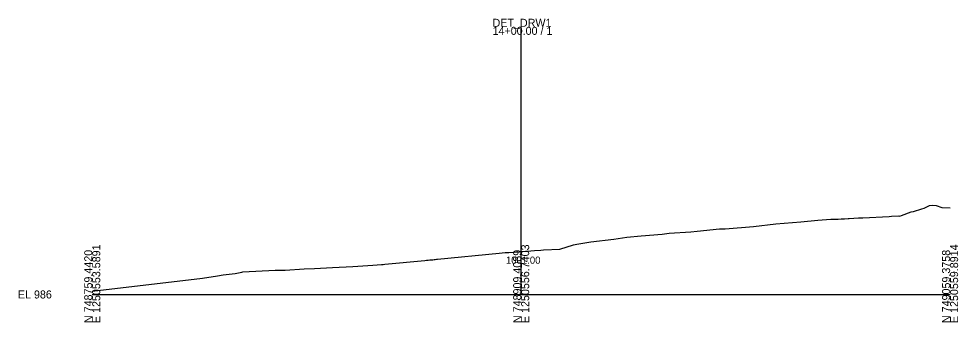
# Model space of a CAD drawing. Extents: x -26 to 303, y -259 to 4096.
# Drawn here: x -25.7 to 302.8, y 3990.3 to 4096.3 of the extents above; entities that cross this region are included whole.
import ezdxf

# ---------------------------------------------------------------- set-up
doc = ezdxf.new("R2010")
doc.units = 0
for name, color, linetype in [('Default', 7, 'Continuous'), ('Exist Cross Section Cell', 7, 'Continuous'), ('Exist XS Center Line Elevation Label', 7, 'Continuous'), ('Exist XS Ground Line', 7, 'Continuous')]:
    doc.layers.add(name, color=color, linetype=linetype)

msp = doc.modelspace()

# ---------------------------------------------------------------- linework, layer by layer
at = {"layer": 'Exist Cross Section Cell'}
for p, q in [((150, 4000), (150, 4093.54)), ((0, 4000), (150, 4000)), ((150, 4000), (300, 4000))]:
    msp.add_line(p, q, dxfattribs=at)
at = {"layer": 'Exist XS Ground Line'}
for p, q in [((290.94, 4030.11), (292.84, 4031.1)), ((292.84, 4031.1), (294.01, 4031.18)), ((294.01, 4031.18), (295.09, 4031.12)), ((295.09, 4031.12), (297.1, 4030.4)), ((282.98, 4027.64), (286.39, 4028.84)), ((286.39, 4028.84), (287.24, 4029.02)), ((287.24, 4029.02), (290.17, 4029.9)), ((290.17, 4029.9), (290.94, 4030.11)), ((297.1, 4030.4), (300, 4030.33)), ((231.2, 4023.81), (239.07, 4024.66)), ((239.07, 4024.66), (247.78, 4025.38)), ((247.78, 4025.38), (253.7, 4026.01)), ((253.7, 4026.01), (258.32, 4026.37)), ((258.32, 4026.37), (260.91, 4026.37)), ((260.91, 4026.37), (261.86, 4026.41)), ((261.86, 4026.41), (263.1, 4026.48)), ((263.1, 4026.48), (264.36, 4026.58)), ((264.36, 4026.58), (264.73, 4026.55)), ((264.73, 4026.55), (267.99, 4026.73)), ((267.99, 4026.73), (269.49, 4026.81)), ((269.49, 4026.81), (278.7, 4027.21)), ((278.7, 4027.21), (279.47, 4027.33)), ((279.47, 4027.33), (282.11, 4027.43)), ((282.11, 4027.43), (282.41, 4027.34)), ((282.41, 4027.34), (282.98, 4027.64)), ((199.32, 4021.05), (201.8, 4021.37)), ((201.8, 4021.37), (209.32, 4021.93)), ((209.32, 4021.93), (211.59, 4022.07)), ((211.59, 4022.07), (219.33, 4022.88)), ((219.33, 4022.88), (221.39, 4022.99)), ((221.39, 4022.99), (231.2, 4023.81)), ((169.41, 4017.62), (174.39, 4018.37)), ((174.39, 4018.37), (182.35, 4019.36)), ((182.35, 4019.36), (186.96, 4019.97)), ((186.96, 4019.97), (192, 4020.52)), ((192, 4020.52), (199.32, 4021.05)), ((144.41, 4014.62), (145.73, 4014.71)), ((145.73, 4014.71), (149.4, 4014.95)), ((149.4, 4014.95), (150, 4015)), ((150, 4015), (153.42, 4015.23)), ((153.42, 4015.23), (154.67, 4015.31)), ((154.67, 4015.31), (156.88, 4015.46)), ((156.88, 4015.46), (157.86, 4015.55)), ((157.86, 4015.55), (163.5, 4015.89)), ((163.5, 4015.89), (168.32, 4017.32)), ((168.32, 4017.32), (169.41, 4017.62)), ((102.34, 4010.58), (116.35, 4011.88)), ((116.35, 4011.88), (116.92, 4011.94)), ((116.92, 4011.94), (117.48, 4012)), ((117.48, 4012), (118.04, 4012.05)), ((118.04, 4012.05), (118.56, 4012.11)), ((118.56, 4012.11), (119.06, 4012.16)), ((119.06, 4012.16), (119.53, 4012.2)), ((119.53, 4012.2), (119.96, 4012.24)), ((119.96, 4012.24), (120.34, 4012.28)), ((120.34, 4012.28), (120.69, 4012.31)), ((120.69, 4012.31), (142.28, 4014.41)), ((142.28, 4014.41), (144.41, 4014.62)), ((52.68, 4007.88), (63.98, 4008.45)), ((63.98, 4008.45), (64.68, 4008.47)), ((64.68, 4008.47), (67.43, 4008.53)), ((67.43, 4008.53), (74.12, 4008.92)), ((74.12, 4008.92), (77.73, 4009.02)), ((77.73, 4009.02), (84.07, 4009.44)), ((84.07, 4009.44), (91.12, 4009.76)), ((91.12, 4009.76), (98.07, 4010.21)), ((98.07, 4010.21), (101.19, 4010.46)), ((101.19, 4010.46), (101.77, 4010.52)), ((101.77, 4010.52), (102.34, 4010.58)), ((0, 4001.19), (38.53, 4005.69)), ((38.53, 4005.69), (43.85, 4006.56)), ((43.85, 4006.56), (45.74, 4006.89)), ((45.74, 4006.89), (49.95, 4007.37)), ((49.95, 4007.37), (52.34, 4007.85)), ((52.34, 4007.85), (52.68, 4007.88))]:
    msp.add_line(p, q, dxfattribs=at)

# ---------------------------------------------------------------- texts
at = {"layer": 'Default'}
msp.add_text('-', height=0.0001, dxfattribs=at).set_placement((0, 4000))
at = {"layer": 'Exist Cross Section Cell'}
for s, p in [('14+00.00 / 1', (140, 4090.74)), ('DET_DRW1', (140, 4093.54)), ('EL 986', (-26, 3998.6))]:
    msp.add_text(s, height=2.8, dxfattribs=at).set_placement(p)
for s, p in [('N 748759.4420', (0, 3990)), ('E 1250553.5891', (2.8, 3990)), ('N 748909.4089', (150, 3990)), ('E 1250556.7403', (152.8, 3990)), ('N 749059.3758', (300, 3990)), ('E 1250559.8914', (302.8, 3990))]:
    msp.add_text(s, height=2.8, rotation=90, dxfattribs=at).set_placement(p)
at = {"layer": 'Exist XS Center Line Elevation Label'}
msp.add_text('1001.00', height=2.5, dxfattribs=at).set_placement((144.67, 4010.75))

doc.saveas('drawing.dxf')
